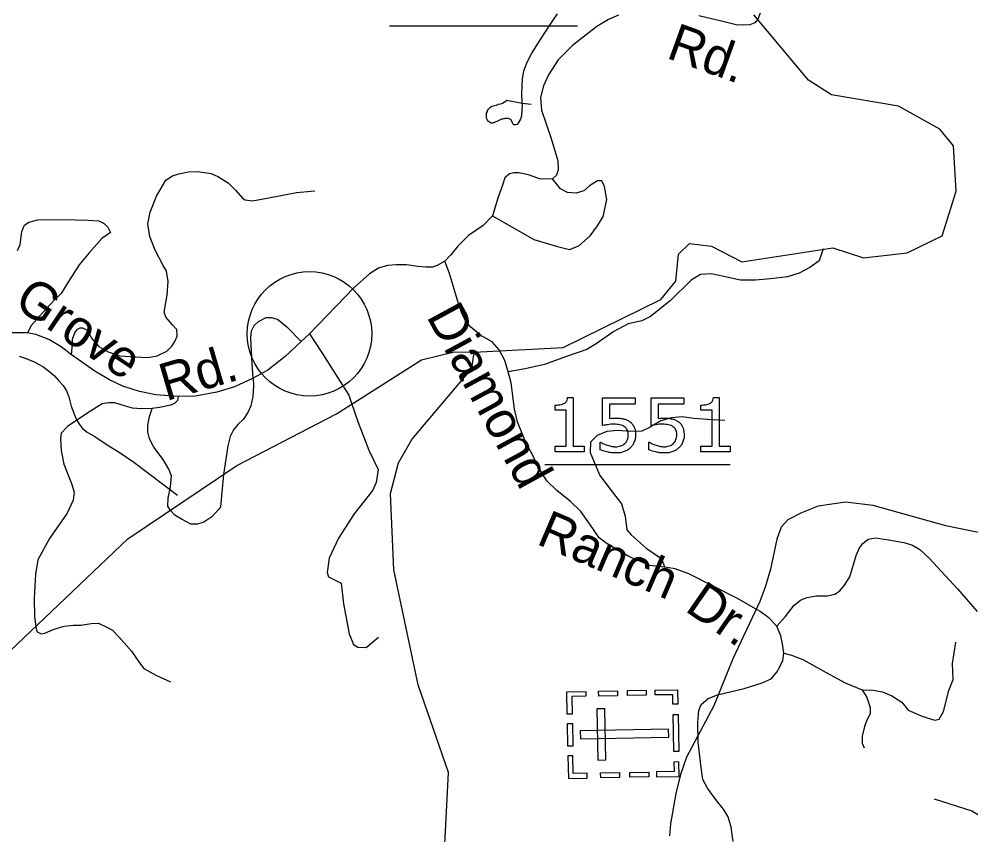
# Model space of a CAD drawing. Extents: x 1190067 to 1192950, y 891516 to 893460.
# Drawn here: x 1191052.1 to 1191128.6, y 893235.3 to 893300.9 of the extents above; entities that cross this region are included whole.
import ezdxf

# ---------------------------------------------------------------- set-up
doc = ezdxf.new("R2010")
doc.units = 0
doc.layers.add('Default', color=7, linetype='Continuous')
doc.layers.add('Prop DSN Text', color=7, linetype='Continuous')

msp = doc.modelspace()

# ---------------------------------------------------------------- linework, layer by layer
at = {"layer": 'Default'}
for p, q in [((1191081.835, 893300.404), (1191096.965, 893300.404)), ((1191091.284, 893294.421), (1191092.504, 893294.178)), ((1191092.504, 893294.178), (1191093.236, 893294.089)), ((1191094.335, 893265.131), (1191109.216, 893265.131))]:
    msp.add_line(p, q, dxfattribs=at)
for points in [[(1191100.242, 893301.25), (1191099.441, 893300.898), (1191098.512, 893300.352), (1191096.557, 893298.813), (1191095.387, 893297.659), (1191094.618, 893296.44), (1191094.234, 893295.574), (1191093.977, 893294.644), (1191094.074, 893293.618), (1191094.827, 893291.341), (1191095.371, 893289.545), (1191095.403, 893288.808), (1191095.275, 893288.391), (1191094.949, 893288.092), (1191094.602, 893288.07), (1191093.897, 893288.102), (1191093.096, 893288.391), (1191092.263, 893288.583), (1191091.846, 893288.583), (1191091.494, 893288.487), (1191091.109, 893288.166), (1191090.917, 893287.589), (1191090.564, 893286.531), (1191090.128, 893285.127), (1191089.379, 893284.35), (1191088.193, 893283.549), (1191087.328, 893282.683), (1191086.783, 893281.977), (1191086.286, 893281.467)], [(1191088.656, 893274.154), (1191095.815, 893274.529), (1191103.653, 893278.393), (1191104.861, 893279.863), (1191105.071, 893282.042), (1191105.963, 893282.883), (1191107.713, 893282.679), (1191110.163, 893281.422), (1191117.478, 893282.54), (1191119.946, 893281.744), (1191123.446, 893282.134), (1191126.263, 893283.513), (1191127.383, 893287.11), (1191127.191, 893290.732), (1191126.071, 893292.076), (1191122.746, 893293.924), (1191117.373, 893294.836), (1191115.518, 893296.022), (1191111.126, 893301.279)], [(1191088.656, 893274.154), (1191095.815, 893274.529), (1191103.653, 893278.393), (1191104.861, 893279.863), (1191105.071, 893282.042), (1191105.963, 893282.883), (1191107.713, 893282.679), (1191110.163, 893281.422), (1191117.478, 893282.54), (1191119.946, 893281.744), (1191123.446, 893282.134), (1191126.263, 893283.513), (1191127.383, 893287.11), (1191127.191, 893290.732), (1191126.071, 893292.076), (1191122.746, 893293.924), (1191117.373, 893294.836), (1191115.518, 893296.022), (1191111.126, 893301.279)], [(1191092.504, 893294.178), (1191092.488, 893294.948), (1191092.506, 893295.58), (1191092.522, 893296.104), (1191092.644, 893296.766), (1191092.906, 893297.46), (1191093.279, 893298.185), (1191093.971, 893299.286), (1191094.337, 893299.837), (1191094.668, 893300.354), (1191094.996, 893300.835), (1191095.358, 893301.352)], [(1191111.651, 893301.411), (1191111.458, 893300.93), (1191111.202, 893300.641), (1191110.817, 893300.481), (1191110.337, 893300.449), (1191109.696, 893300.481), (1191108.638, 893300.737), (1191106.716, 893301.186)], [(1191092.504, 893294.178), (1191092.484, 893293.479), (1191092.445, 893293.339), (1191092.441, 893293.165), (1191092.364, 893292.885), (1191092.29, 893292.747), (1191092.215, 893292.61), (1191092.107, 893292.472), (1191092.001, 893292.44), (1191091.895, 893292.443), (1191091.826, 893292.443), (1191091.757, 893292.517), (1191091.725, 893292.587), (1191091.626, 893292.836), (1191091.556, 893292.872), (1191091.418, 893292.946), (1191091.348, 893292.948), (1191091.278, 893292.949), (1191091.138, 893292.955), (1191091.068, 893292.921), (1191090.998, 893292.922), (1191090.927, 893292.89), (1191090.857, 893292.892), (1191090.749, 893292.824), (1191090.537, 893292.725), (1191090.326, 893292.66), (1191090.252, 893292.592), (1191090.148, 893292.596), (1191090.078, 893292.562), (1191090.008, 893292.564), (1191089.87, 893292.637), (1191089.802, 893292.711), (1191089.733, 893292.817), (1191089.667, 893292.922), (1191089.633, 893292.994), (1191089.637, 893293.1), (1191089.64, 893293.204), (1191089.642, 893293.274), (1191089.646, 893293.38), (1191089.719, 893293.516), (1191089.721, 893293.588), (1191089.793, 893293.69), (1191089.9, 893293.793), (1191089.972, 893293.861), (1191090.08, 893293.929), (1191090.186, 893293.959), (1191090.431, 893294.024), (1191090.609, 893294.089), (1191090.785, 893294.119), (1191090.927, 893294.186), (1191091.14, 893294.32), (1191091.284, 893294.421)], [(1191056.282, 893273.945), (1191056.33, 893274.523), (1191056.354, 893275.197), (1191056.547, 893275.702), (1191056.763, 893276.015), (1191056.98, 893276.111), (1191057.172, 893276.111), (1191057.557, 893275.919), (1191057.894, 893275.269), (1191058.471, 893274.619), (1191059.24, 893274.186), (1191060.178, 893273.873), (1191061.429, 893273.777), (1191062.415, 893273.729), (1191063.161, 893273.873), (1191063.954, 893274.234), (1191064.339, 893274.643), (1191064.58, 893275.004), (1191064.772, 893275.437), (1191064.748, 893275.967), (1191064.411, 893276.352), (1191063.858, 893276.978), (1191063.738, 893277.363), (1191063.978, 893278.735), (1191064.05, 893279.842), (1191063.906, 893280.66), (1191063.618, 893281.189), (1191063.016, 893282.369), (1191062.583, 893283.452), (1191062.427, 893284.463), (1191062.595, 893285.425), (1191063.125, 893286.701), (1191063.87, 893287.977), (1191064.399, 893288.338), (1191064.904, 893288.506), (1191065.674, 893288.65), (1191066.419, 893288.674), (1191067.502, 893288.53), (1191068.031, 893288.289), (1191068.873, 893287.76), (1191069.498, 893287.158), (1191070.027, 893286.532), (1191070.244, 893286.412), (1191070.821, 893286.316), (1191072.264, 893286.581), (1191074.356, 893286.99), (1191075.835, 893287.134)], [(1191090.128, 893285.127), (1191093.442, 893283.218), (1191095.35, 893282.665), (1191096.304, 893282.413), (1191097.058, 893282.715), (1191097.962, 893283.519), (1191098.564, 893284.323), (1191099.016, 893285.077), (1191099.318, 893286.434), (1191099.117, 893287.489), (1191098.916, 893287.941), (1191098.564, 893287.941), (1191097.911, 893287.539), (1191097.459, 893287.137), (1191096.857, 893286.936), (1191096.154, 893286.987), (1191095.601, 893287.288), (1191094.949, 893288.092)], [(1191051.929, 893282.321), (1191052.145, 893282.826), (1191052.29, 893283.861), (1191052.506, 893284.366), (1191052.843, 893284.607), (1191053.588, 893284.8), (1191055.609, 893284.824), (1191057.605, 893284.776), (1191058.483, 893284.703), (1191058.916, 893284.511), (1191059.204, 893284.198), (1191059.421, 893283.789)], [(1191059.421, 893283.789), (1191058.723, 893283.283), (1191057.713, 893282.152), (1191056.895, 893281.165), (1191056.03, 893279.842), (1191055.452, 893278.879), (1191054.875, 893278.325), (1191053.709, 893277.05), (1191053.059, 893276.328), (1191052.747, 893275.702)], [(1191116.693, 893282.464), (1191116.392, 893281.509), (1191115.639, 893280.956), (1191114.785, 893280.504), (1191113.831, 893280.202), (1191112.475, 893280.052), (1191111.27, 893279.951), (1191110.064, 893279.951), (1191108.708, 893280.253), (1191107.704, 893280.454), (1191106.85, 893280.403), (1191106.097, 893279.951), (1191104.39, 893278.293), (1191102.833, 893277.036), (1191102.13, 893276.685), (1191101.025, 893276.433), (1191099.87, 893275.83), (1191098.464, 893274.825), (1191097.711, 893274.373), (1191096.003, 893273.77), (1191094.296, 893273.167), (1191092.739, 893272.815), (1191091.383, 893272.564)], [(1191086.286, 893281.467), (1191085.672, 893281.117), (1191085.311, 893280.997), (1191084.782, 893280.997), (1191084.109, 893281.045), (1191083.219, 893281.165), (1191082.401, 893281.19), (1191081.68, 893281.117), (1191080.958, 893280.901), (1191080.237, 893280.467), (1191078.986, 893279.336), (1191075.413, 893275.629), (1191074.74, 893275.025), (1191073.466, 893273.801), (1191072.071, 893272.718), (1191070.896, 893272.057), (1191069.378, 893271.37), (1191067.959, 893270.937), (1191066.227, 893270.624), (1191064.866, 893270.593), (1191063.064, 893270.72), (1191061.742, 893270.985), (1191060.419, 893271.418), (1191059.337, 893271.924), (1191058.158, 893272.621), (1191056.282, 893273.945), (1191055.44, 893274.595), (1191054.454, 893275.173), (1191053.408, 893275.582), (1191052.747, 893275.702), (1191051.436, 893275.702)], [(1191112.964, 893252.126), (1191112.369, 893252.776), (1191111.647, 893253.31), (1191109.828, 893254.346), (1191105.907, 893256.323), (1191104.809, 893256.731), (1191103.958, 893256.868), (1191102.77, 893257.014), (1191101.076, 893257.736), (1191099.351, 893258.74), (1191098.692, 893259.242), (1191097.939, 893260.341), (1191097.218, 893261.346), (1191096.402, 893262.162), (1191095.289, 893263.041), (1191094.504, 893263.794), (1191094.097, 893264.422), (1191092.716, 893267.09), (1191092.12, 893268.565), (1191091.901, 893269.57), (1191091.619, 893271.704), (1191091.383, 893272.564), (1191091.101, 893273.493), (1191090.662, 893274.341), (1191090.097, 893275), (1191089.187, 893275.502), (1191088.372, 893276.162), (1191087.996, 893276.601), (1191087.65, 893277.26), (1191087.368, 893278.139), (1191086.655, 893280.478), (1191086.286, 893281.467)], [(1191070.896, 893272.057), (1191070.779, 893273.678), (1191070.701, 893275.318), (1191070.759, 893275.885), (1191070.955, 893276.295), (1191071.306, 893276.627), (1191071.93, 893276.939), (1191072.34, 893276.939), (1191072.828, 893276.802), (1191073.589, 893276.197), (1191074.74, 893275.025)], [(1191075.413, 893275.629), (1191076.438, 893274.069), (1191078.565, 893270.69), (1191078.799, 893270.046), (1191079.33, 893268.493), (1191080.184, 893266.282), (1191080.937, 893264.724), (1191080.762, 893263.669), (1191080.511, 893263.066), (1191079.004, 893261.156), (1191077.749, 893259.196), (1191076.995, 893257.588), (1191076.845, 893256.432), (1191076.945, 893256.081), (1191077.949, 893255.578), (1191078.15, 893253.92), (1191078.602, 893251.507), (1191078.954, 893250.653), (1191079.305, 893250.452), (1191079.958, 893250.402), (1191080.963, 893251.256)], [(1191029.786, 893212.54), (1191030.486, 893217.064), (1191033.408, 893222.808), (1191035.51, 893224.95), (1191036.436, 893226.826), (1191036.7, 893231.015), (1191040.846, 893238.801), (1191041.511, 893241.834), (1191042.736, 893243.706), (1191048.528, 893247.495), (1191060.813, 893259.143), (1191069.581, 893265.056), (1191077.578, 893269.205), (1191084.403, 893273.549), (1191087.046, 893274.186), (1191088.656, 893274.154)], [(1191029.786, 893212.54), (1191030.486, 893217.064), (1191033.408, 893222.808), (1191035.51, 893224.95), (1191036.436, 893226.826), (1191036.7, 893231.015), (1191040.846, 893238.801), (1191041.511, 893241.834), (1191042.736, 893243.706), (1191048.528, 893247.495), (1191060.813, 893259.143), (1191069.581, 893265.056), (1191077.578, 893269.205), (1191084.403, 893273.549), (1191087.046, 893274.186), (1191088.656, 893274.154)], [(1191097.18, 893168.682), (1191094.502, 893171.955), (1191090.495, 893175.136), (1191086.417, 893180.675), (1191081.027, 893186.355), (1191077.002, 893194.477), (1191078.297, 893198.53), (1191080.433, 893202.394), (1191080.783, 893204.282), (1191081.202, 893214.385), (1191081.813, 893215.809), (1191085.751, 893220.671), (1191086.398, 893222.956), (1191085.962, 893228.364), (1191086.573, 893240.358), (1191084.141, 893247.416), (1191082.198, 893256.647), (1191081.918, 893262.799), (1191082.566, 893265.256), (1191083.651, 893267.132), (1191088.463, 893272.835), (1191088.656, 893274.154)], [(1191097.18, 893168.682), (1191094.502, 893171.955), (1191090.495, 893175.136), (1191086.417, 893180.675), (1191081.027, 893186.355), (1191077.002, 893194.477), (1191078.297, 893198.53), (1191080.433, 893202.394), (1191080.783, 893204.282), (1191081.202, 893214.385), (1191081.813, 893215.809), (1191085.751, 893220.671), (1191086.398, 893222.956), (1191085.962, 893228.364), (1191086.573, 893240.358), (1191084.141, 893247.416), (1191082.198, 893256.647), (1191081.918, 893262.799), (1191082.566, 893265.256), (1191083.651, 893267.132), (1191088.463, 893272.835), (1191088.656, 893274.154)], [(1191052.061, 893273.837), (1191052.547, 893273.685), (1191053.275, 893273.385), (1191053.964, 893273.016), (1191054.445, 893272.651), (1191054.924, 893272.253), (1191055.265, 893271.86), (1191055.604, 893271.465), (1191055.873, 893271.037), (1191056.071, 893270.577), (1191056.259, 893269.802), (1191056.521, 893269.129), (1191056.686, 893268.704), (1191056.921, 893268.347), (1191057.158, 893268.026), (1191057.535, 893267.735), (1191058.225, 893267.332), (1191059.153, 893266.711), (1191060.118, 893266.124), (1191061.288, 893265.322), (1191064.789, 893262.67)], [(1191070.896, 893272.057), (1191070.916, 893271.413), (1191070.857, 893270.593), (1191070.701, 893269.851), (1191070.447, 893269.304), (1191070.096, 893268.757), (1191069.647, 893268.328), (1191069.296, 893267.918), (1191069.023, 893267.371), (1191068.847, 893266.629), (1191068.496, 893264.325), (1191068.32, 893262.313), (1191068.252, 893261.728), (1191068.115, 893261.532), (1191067.549, 893260.927), (1191066.925, 893260.478), (1191066.398, 893260.322), (1191065.871, 893260.341), (1191065.169, 893260.693), (1191064.583, 893261.064), (1191064.232, 893261.415), (1191064.018, 893261.786), (1191064.057, 893262.431), (1191064.252, 893263.329), (1191064.31, 893264.227), (1191064.096, 893264.754), (1191063.647, 893265.516), (1191062.886, 893266.512), (1191062.564, 893267.176), (1191062.427, 893267.761), (1191062.427, 893268.269), (1191062.544, 893268.972), (1191062.759, 893269.616)], [(1191064.866, 893270.593), (1191064.808, 893270.28), (1191064.574, 893270.046), (1191064.261, 893269.89), (1191063.344, 893269.714), (1191062.759, 893269.616), (1191061.881, 893269.597), (1191061.178, 893269.656), (1191060.612, 893269.812), (1191059.773, 893270.085), (1191059.286, 893270.085), (1191058.759, 893270.007), (1191057.588, 893269.285), (1191055.968, 893268.191), (1191055.441, 893267.644), (1191055.402, 893267.195), (1191055.441, 893266.238), (1191055.656, 893265.164), (1191056.281, 893263.602), (1191056.505, 893262.899), (1191056.427, 893262.255), (1191055.939, 893261.22), (1191054.515, 893259.17), (1191053.568, 893257.451), (1191053.393, 893256.299), (1191053.275, 893254.385), (1191053.314, 893252.882), (1191053.441, 893251.945), (1191053.519, 893251.671), (1191053.832, 893251.515), (1191054.124, 893251.574), (1191054.807, 893251.866), (1191055.685, 893252.14), (1191056.407, 893252.198), (1191057.032, 893252.198), (1191057.871, 893252.355), (1191058.456, 893252.374), (1191059.12, 893252.042), (1191059.569, 893251.808), (1191060.095, 893251.281), (1191061.091, 893250.109), (1191061.754, 893249.191), (1191062.086, 893248.723), (1191063.061, 893248.195), (1191064.242, 893247.649)], [(1191096.162, 893270.511), (1191096.615, 893270.511), (1191096.615, 893266.59), (1191097.502, 893266.59), (1191097.502, 893266.146)], [(1191098.975, 893268.256), (1191098.975, 893270.496), (1191101.592, 893270.496), (1191101.592, 893269.985), (1191099.536, 893269.985), (1191099.536, 893268.829)], [(1191102.879, 893268.256), (1191102.879, 893270.496), (1191105.496, 893270.496), (1191105.496, 893269.985), (1191103.44, 893269.985), (1191103.44, 893268.829)], [(1191107.876, 893270.511), (1191108.329, 893270.511), (1191108.329, 893266.59), (1191109.216, 893266.59), (1191109.216, 893266.146)], [(1191097.502, 893266.146), (1191095.148, 893266.146), (1191095.148, 893266.59), (1191096.054, 893266.59), (1191096.054, 893269.506), (1191095.148, 893269.506), (1191095.148, 893269.903)], [(1191109.216, 893266.146), (1191106.862, 893266.146), (1191106.862, 893266.59), (1191107.768, 893266.59), (1191107.768, 893269.506), (1191106.862, 893269.506), (1191106.862, 893269.903)], [(1191108.801, 893268.671), (1191107.779, 893268.712), (1191106.307, 893268.835), (1191105.367, 893268.958), (1191104.509, 893268.876), (1191103.65, 893268.63), (1191102.792, 893268.14), (1191102.138, 893267.812), (1191101.239, 893267.771), (1191100.176, 893267.853), (1191099.317, 893267.771), (1191098.541, 893267.444), (1191098.009, 893266.912), (1191097.968, 893266.094), (1191098.377, 893265.113), (1191098.745, 893264.254), (1191099.767, 893262.904), (1191100.503, 893261.963), (1191100.789, 893260.981), (1191100.912, 893259.877), (1191101.279, 893259.468), (1191102.465, 893258.404), (1191103.65, 893257.586), (1191103.855, 893257.136), (1191103.958, 893256.868)], [(1191098.786, 893266.308), (1191098.786, 893266.924), (1191098.827, 893266.924)], [(1191102.691, 893266.308), (1191102.691, 893266.924), (1191102.732, 893266.924)], [(1191125.633, 893238.257), (1191128.662, 893237.278), (1191131.69, 893235.493), (1191146.563, 893235.369), (1191148.768, 893236.015), (1191150.712, 893237.756), (1191151.446, 893243.256), (1191152.216, 893244.964), (1191152.62, 893248.748), (1191153.231, 893249.77), (1191153.477, 893253.842), (1191156.031, 893256.549), (1191156.575, 893260.044), (1191159.287, 893263.033), (1191163.673, 893265.297)], [(1191134.664, 893258.531), (1191126.561, 893260.2), (1191120.718, 893261.818), (1191118.495, 893262.098), (1191116.307, 893261.788), (1191114.96, 893261.23), (1191113.857, 893260.668), (1191113.315, 893260.09), (1191112.965, 893259.123), (1191112.457, 893256.708), (1191112.071, 893255.339), (1191111.617, 893254.117), (1191109.446, 893249.51), (1191107.907, 893245.731), (1191105.72, 893241.606), (1191105.23, 893240.196), (1191104.862, 893238.676), (1191104.424, 893236.247), (1191104.354, 893235.262)], [(1191112.964, 893252.126), (1191113.64, 893252.884), (1191114.371, 893253.804), (1191114.885, 893254.211), (1191115.399, 893254.427), (1191116.156, 893254.562), (1191117.049, 893254.562), (1191117.644, 893254.698), (1191118.05, 893254.969), (1191118.429, 893255.429), (1191118.835, 893256.106), (1191119.349, 893257.811), (1191119.619, 893258.434), (1191119.89, 893258.786), (1191120.322, 893259.111), (1191120.918, 893259.219), (1191121.946, 893259.057), (1191123.19, 893258.867), (1191123.894, 893258.65), (1191124.462, 893258.299), (1191125.219, 893257.595), (1191127.492, 893255.131), (1191129.088, 893253.317)], [(1191109.465, 893234.817), (1191109.301, 893235.968), (1191109.054, 893236.789), (1191108.701, 893237.414), (1191108.126, 893238.104), (1191107.412, 893239.091), (1191107.018, 893239.814), (1191106.886, 893240.767), (1191106.656, 893242.805), (1191106.623, 893244.383), (1191106.706, 893245.337), (1191106.903, 893245.83), (1191107.461, 893246.323), (1191108.217, 893246.619), (1191110.352, 893247.112), (1191111.797, 893247.572), (1191112.52, 893247.901), (1191112.98, 893248.427), (1191113.21, 893248.854), (1191113.473, 893249.38), (1191113.539, 893249.957), (1191113.44, 893250.695), (1191113.309, 893251.352), (1191112.964, 893252.126)], [(1191119.835, 893247.009), (1191120.728, 893246.982), (1191121.459, 893246.847), (1191122.216, 893246.522), (1191123.028, 893246.008), (1191123.542, 893245.385), (1191124.705, 893244.87), (1191125.679, 893244.573), (1191126.031, 893244.654), (1191126.383, 893245.277), (1191126.815, 893246.955), (1191127.14, 893247.848), (1191127.086, 893249.121), (1191127.356, 893250.854)], [(1191113.539, 893249.957), (1191114.154, 893249.798), (1191115.074, 893249.446), (1191116.941, 893248.39), (1191118.483, 893247.578), (1191119.835, 893247.009), (1191120.214, 893246.387), (1191120.485, 893245.601), (1191120.485, 893245.087), (1191120.214, 893244.573), (1191120.025, 893244.058), (1191119.835, 893243.273), (1191119.835, 893242.732), (1191119.998, 893242.353)]]:
    msp.add_lwpolyline(points, dxfattribs=at)
for points in [[(1191097.613, 893246.886), (1191097.62, 893246.489), (1191096.493, 893246.468), (1191096.519, 893245.049), (1191096.13, 893245.042), (1191096.097, 893246.858)], [(1191100.177, 893246.533), (1191098.661, 893246.505), (1191098.654, 893246.904), (1191100.17, 893246.931)], [(1191102.484, 893246.574), (1191100.968, 893246.546), (1191100.961, 893246.945), (1191102.477, 893246.972)], [(1191105.027, 893245.858), (1191104.625, 893245.851), (1191104.611, 893246.62), (1191103.197, 893246.595), (1191103.19, 893246.984), (1191105.006, 893247.017)], [(1191098.577, 893241.36), (1191099.231, 893241.372), (1191099.156, 893245.492), (1191098.502, 893245.481)], [(1191104.694, 893242.054), (1191104.64, 893245.023), (1191105.039, 893245.03), (1191105.093, 893242.061)], [(1191096.175, 893242.481), (1191096.142, 893244.295), (1191096.541, 893244.302), (1191096.574, 893242.488)], [(1191097.178, 893243.723), (1191097.19, 893243.069), (1191104.286, 893243.198), (1191104.274, 893243.851)], [(1191097.737, 893239.916), (1191097.73, 893240.313), (1191096.603, 893240.293), (1191096.578, 893241.712), (1191096.188, 893241.705), (1191096.221, 893239.889)], [(1191105.109, 893241.208), (1191104.707, 893241.2), (1191104.721, 893240.431), (1191103.307, 893240.405), (1191103.314, 893240.015), (1191105.13, 893240.048)], [(1191100.332, 893239.963), (1191098.817, 893239.935), (1191098.809, 893240.334), (1191100.325, 893240.361)], [(1191102.684, 893240.005), (1191101.169, 893239.977), (1191101.162, 893240.376), (1191102.677, 893240.403)]]:
    msp.add_lwpolyline(points, close=True, dxfattribs=at)
for points in [[(1191095.148, 893269.903), (1191095.332, 893269.903), (1191095.542, 893269.934), (1191095.753, 893269.965), (1191095.861, 893270.023), (1191095.995, 893270.096), (1191096.073, 893270.208), (1191096.15, 893270.321), (1191096.162, 893270.511)], [(1191106.862, 893269.903), (1191107.046, 893269.903), (1191107.256, 893269.934), (1191107.467, 893269.965), (1191107.575, 893270.023), (1191107.709, 893270.096), (1191107.787, 893270.208), (1191107.864, 893270.321), (1191107.876, 893270.511)], [(1191099.536, 893268.829), (1191099.661, 893268.841), (1191099.793, 893268.846), (1191099.925, 893268.852), (1191100.021, 893268.852), (1191100.375, 893268.852), (1191100.641, 893268.792), (1191100.907, 893268.732), (1191101.129, 893268.58), (1191101.363, 893268.42), (1191101.491, 893268.165), (1191101.62, 893267.911), (1191101.62, 893267.528)], [(1191103.44, 893268.829), (1191103.566, 893268.841), (1191103.698, 893268.846), (1191103.829, 893268.852), (1191103.926, 893268.852), (1191104.279, 893268.852), (1191104.545, 893268.792), (1191104.811, 893268.732), (1191105.034, 893268.58), (1191105.267, 893268.42), (1191105.396, 893268.165), (1191105.525, 893267.911), (1191105.525, 893267.528)], [(1191098.827, 893266.924), (1191099.067, 893266.772), (1191099.388, 893266.665), (1191099.71, 893266.558), (1191100.019, 893266.558), (1191100.227, 893266.558), (1191100.421, 893266.617), (1191100.615, 893266.675), (1191100.767, 893266.822), (1191100.896, 893266.948), (1191100.961, 893267.124), (1191101.027, 893267.299), (1191101.027, 893267.531), (1191101.027, 893267.756), (1191100.95, 893267.911), (1191100.872, 893268.066), (1191100.735, 893268.16), (1191100.583, 893268.271), (1191100.366, 893268.317), (1191100.148, 893268.362), (1191099.88, 893268.362), (1191099.623, 893268.362), (1191099.385, 893268.327), (1191099.147, 893268.291), (1191098.975, 893268.256)], [(1191102.732, 893266.924), (1191102.972, 893266.772), (1191103.293, 893266.665), (1191103.614, 893266.558), (1191103.924, 893266.558), (1191104.131, 893266.558), (1191104.326, 893266.617), (1191104.52, 893266.675), (1191104.672, 893266.822), (1191104.8, 893266.948), (1191104.866, 893267.124), (1191104.932, 893267.299), (1191104.932, 893267.531), (1191104.932, 893267.756), (1191104.854, 893267.911), (1191104.777, 893268.066), (1191104.64, 893268.16), (1191104.488, 893268.271), (1191104.27, 893268.317), (1191104.053, 893268.362), (1191103.784, 893268.362), (1191103.527, 893268.362), (1191103.289, 893268.327), (1191103.052, 893268.291), (1191102.879, 893268.256)], [(1191101.62, 893267.528), (1191101.62, 893267.224), (1191101.509, 893266.946), (1191101.398, 893266.668), (1191101.205, 893266.478), (1191100.995, 893266.273), (1191100.704, 893266.164), (1191100.414, 893266.054), (1191100.031, 893266.054), (1191099.675, 893266.054), (1191099.344, 893266.128), (1191099.014, 893266.203), (1191098.786, 893266.308)], [(1191105.525, 893267.528), (1191105.525, 893267.224), (1191105.414, 893266.946), (1191105.303, 893266.668), (1191105.11, 893266.478), (1191104.9, 893266.273), (1191104.609, 893266.164), (1191104.318, 893266.054), (1191103.936, 893266.054), (1191103.579, 893266.054), (1191103.249, 893266.128), (1191102.919, 893266.203), (1191102.691, 893266.308)]]:
    msp.add_open_spline(points, degree=3, dxfattribs=at)
at = {"layer": 'Prop DSN Text'}
msp.add_circle((1191075.413, 893275.629), 5, dxfattribs=at)
msp.add_circle((1191075.413, 893275.629), 5, dxfattribs=at)

# ---------------------------------------------------------------- texts
at = {"layer": 'Default'}
for s, rotation, p in [('Rd.', 340.14579, (1191104.006, 893297.842)), ('Grove', 326.18728, (1191051.53, 893277.897)), ('Diamond', 298.49421, (1191084.772, 893277.047)), ('Rd.', 16.37122, (1191063.875, 893270.211)), ('Ranch', 336.88263, (1191093.56, 893258.77)), ('Dr.', 325.28104, (1191105.494, 893253.414))]:
    msp.add_text(s, height=3, rotation=rotation, dxfattribs=at).set_placement(p)

doc.saveas('drawing.dxf')
